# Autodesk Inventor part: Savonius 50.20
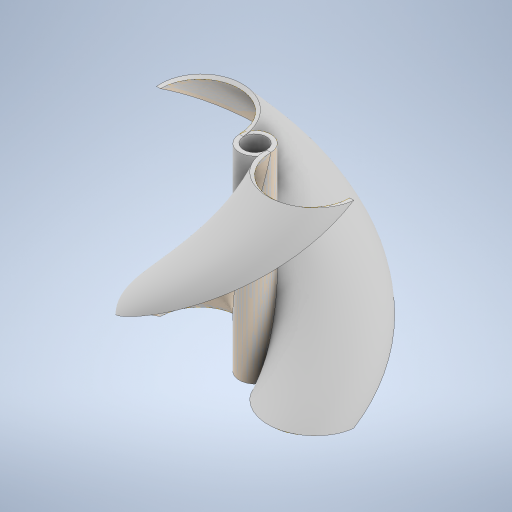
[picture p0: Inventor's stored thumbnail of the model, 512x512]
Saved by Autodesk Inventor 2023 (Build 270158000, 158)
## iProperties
Created: 2025-05
Part Number: Savonius 50.20
Material: Generic
Document SubType Name: Modeling
Designer: Brecht.Carpentier
Density: 1 g/cm^3
Appearance: Default
Author: Brecht.Carpentier
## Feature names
1. Extrusion1
## Parameters: d2 = 25 mm, d3 = 0, d4 = 5.8 mm, d5 = 8 mm, d9 = 0, d12 = 0, d13 = 0, d14 = 1 mm, d15 = 1 mm, d18 = 1 mm, d19 = 1 mm
